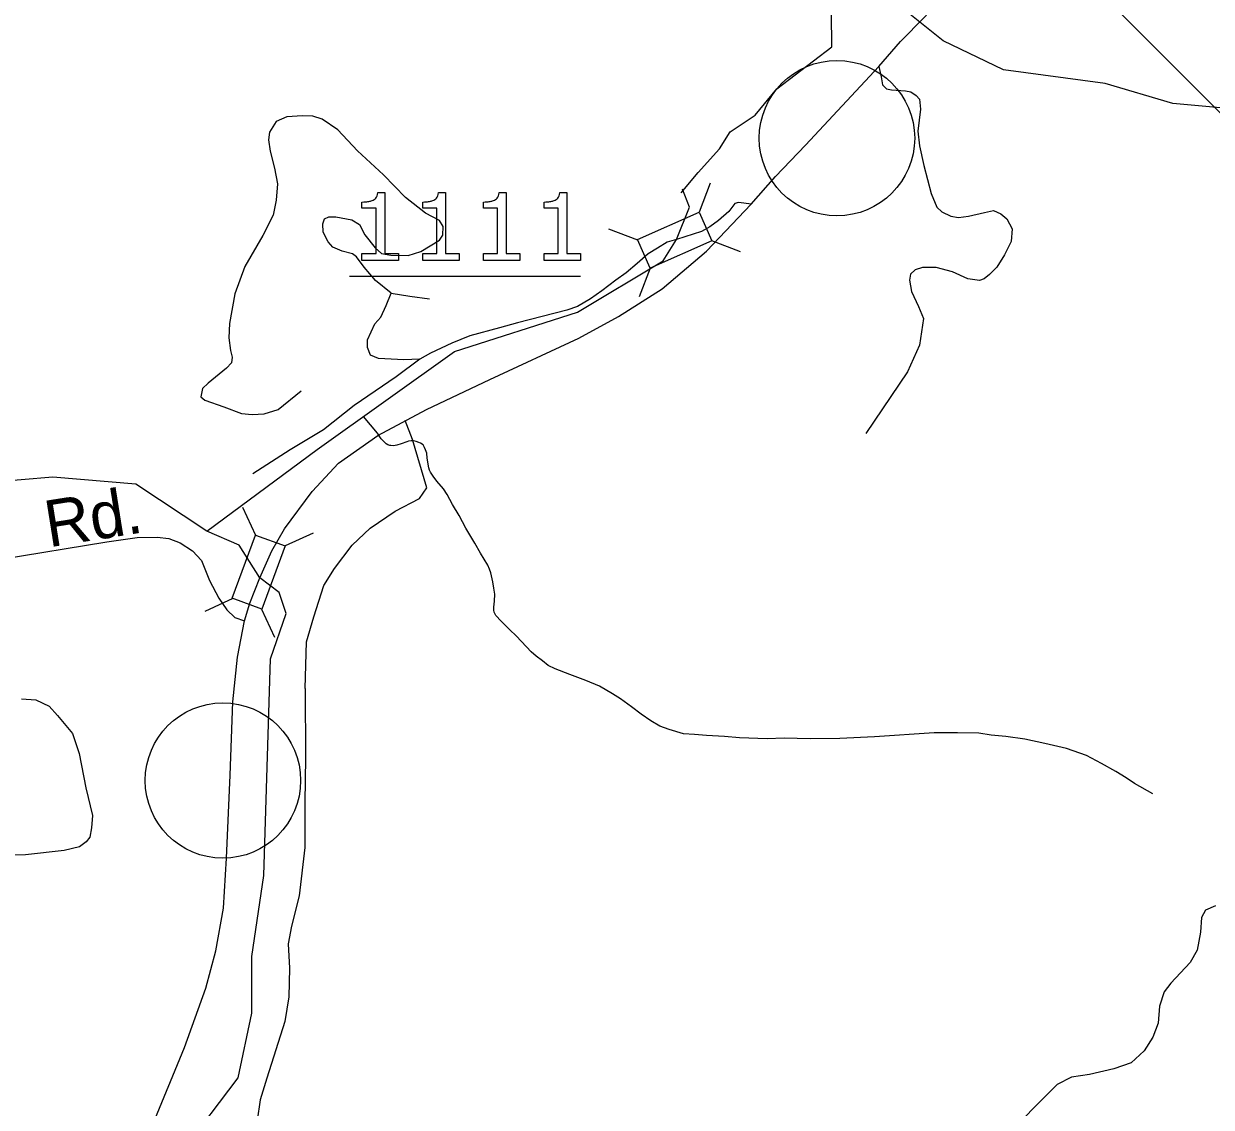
# Model space of a CAD drawing. Extents: x 1190067 to 1192950, y 891516 to 893460.
# Drawn here: x 1190882.9 to 1190959.3, y 893231.2 to 893300.9 of the extents above; entities that cross this region are included whole.
import ezdxf

# ---------------------------------------------------------------- set-up
doc = ezdxf.new("R2010")
doc.units = 0
doc.layers.add('Default', color=7, linetype='Continuous')
doc.layers.add('Prop DSN Text', color=7, linetype='Continuous')

msp = doc.modelspace()

# ---------------------------------------------------------------- linework, layer by layer
at = {"layer": 'Default'}
for p, q in [((1190960.312, 893294.828), (1190948.657, 893306.483)), ((1190927.1, 893290.667), (1190926.392, 893288.817)), ((1190922.445, 893287.017), (1190920.595, 893287.725)), ((1190929.067, 893286.258), (1190927.217, 893286.967)), ((1190923.252, 893285.208), (1190922.544, 893283.358)), ((1190903.895, 893284.692), (1190918.776, 893284.692)), ((1190897.026, 893269.823), (1190897.856, 893268.025)), ((1190901.556, 893268.154), (1190899.757, 893267.324)), ((1190896.391, 893263.941), (1190894.592, 893263.111)), ((1190898.249, 893263.257), (1190899.079, 893261.459))]:
    msp.add_line(p, q, dxfattribs=at)
for points in [[(1190929.742, 893289.335), (1190931.321, 893291.099), (1190933.231, 893293.132), (1190937.963, 893298.187), (1190939.364, 893299.797), (1190940.907, 893301.365), (1190943.539, 893304.28), (1190944.886, 893306.094), (1190945.938, 893307.784), (1190946.673, 893309.328), (1190947.395, 893311.141), (1190947.934, 893312.978), (1190948.717, 893316.163), (1190949.501, 893318.834), (1190950.113, 893320.28), (1190950.799, 893321.411)], [(1190925.252, 893290.053), (1190926.327, 893291.359), (1190927.709, 893292.896), (1190928.4, 893293.972), (1190930.013, 893295.048), (1190931.395, 893296.739), (1190934.934, 893299.456), (1190934.899, 893303.824)], [(1190980.698, 893248.449), (1190979.491, 893247.036), (1190979.736, 893245.425), (1190981.503, 893246.077), (1190983.883, 893247.925), (1190988.976, 893247.078), (1190989.711, 893247.637), (1190989.396, 893251.894), (1190988.398, 893253.063), (1190988.573, 893253.634), (1190985.196, 893258.527), (1190981.713, 893269.914), (1190981.344, 893272.506), (1190978.598, 893279.282), (1190976.358, 893282.428), (1190970.811, 893287.999), (1190966.348, 893289.983), (1190961.814, 893295.359), (1190956.881, 893295.802), (1190952.522, 893297.095), (1190945.977, 893297.974), (1190942.094, 893299.83), (1190938.664, 893302.599), (1190934.899, 893303.824)], [(1190980.698, 893248.449), (1190979.491, 893247.036), (1190979.736, 893245.425), (1190981.503, 893246.077), (1190983.883, 893247.925), (1190988.976, 893247.078), (1190989.711, 893247.637), (1190989.396, 893251.894), (1190988.398, 893253.063), (1190988.573, 893253.634), (1190985.196, 893258.527), (1190981.713, 893269.914), (1190981.344, 893272.506), (1190978.598, 893279.282), (1190976.358, 893282.428), (1190970.811, 893287.999), (1190966.348, 893289.983), (1190961.814, 893295.359), (1190956.881, 893295.802), (1190952.522, 893297.095), (1190945.977, 893297.974), (1190942.094, 893299.83), (1190938.664, 893302.599), (1190934.899, 893303.824)], [(1190937.963, 893298.187), (1190938.113, 893297.525), (1190938.204, 893297.013), (1190938.444, 893296.742), (1190938.775, 893296.682), (1190939.677, 893296.622), (1190940.008, 893296.562), (1190940.369, 893296.321), (1190940.58, 893296.08), (1190940.64, 893295.448), (1190940.459, 893294.034), (1190940.58, 893293.071), (1190940.85, 893291.807), (1190941.331, 893290.001), (1190941.692, 893289.128), (1190942.023, 893288.827), (1190942.595, 893288.556), (1190943.076, 893288.466), (1190943.737, 893288.556), (1190944.76, 893288.797), (1190945.331, 893288.917), (1190945.813, 893288.707), (1190946.204, 893288.376), (1190946.534, 893287.744), (1190946.474, 893286.931), (1190946.038, 893286.058), (1190945.557, 893285.276), (1190945.076, 893284.794), (1190944.745, 893284.523), (1190944.444, 893284.403), (1190943.692, 893284.523), (1190942.7, 893284.975), (1190941.647, 893285.246), (1190940.775, 893285.246), (1190940.294, 893285.095), (1190939.993, 893284.824), (1190939.933, 893284.433), (1190940.053, 893283.711), (1190940.504, 893282.748), (1190940.835, 893281.965), (1190940.58, 893280.25), (1190939.798, 893278.534), (1190937.121, 893274.561)], [(1190906.586, 893283.602), (1190905.583, 893284.41), (1190904.848, 893285.268), (1190904.358, 893285.929), (1190904.089, 893286.125), (1190903.428, 893286.297), (1190902.84, 893286.566), (1190902.522, 893286.909), (1190902.216, 893287.522), (1190902.191, 893288.061), (1190902.289, 893288.379), (1190902.583, 893288.502), (1190903.024, 893288.502), (1190904.052, 893288.306), (1190904.542, 893288.012), (1190904.885, 893287.35), (1190905.546, 893286.517), (1190905.962, 893286.15), (1190906.574, 893286.052), (1190907.676, 893286.027), (1190908.484, 893286.272), (1190909.684, 893287.007), (1190909.904, 893287.326), (1190909.928, 893287.889), (1190909.684, 893288.281), (1190908.802, 893288.747), (1190907.505, 893289.751), (1190906.084, 893291.221), (1190904.42, 893292.765), (1190903.146, 893294.113), (1190902.155, 893294.799), (1190901.543, 893294.995), (1190900.882, 893295.019), (1190899.878, 893294.946), (1190899.192, 893294.652), (1190898.751, 893293.966), (1190898.703, 893293.475), (1190898.8, 893292.74), (1190899.07, 893291.638), (1190899.266, 893290.633), (1190899.192, 893289.58), (1190898.996, 893288.624), (1190898.335, 893287.301), (1190897.172, 893285.317), (1190896.536, 893283.553), (1190896.193, 893281.641), (1190896.132, 893280.71), (1190896.254, 893279.902), (1190896.352, 893279.485), (1190896.303, 893279.118), (1190895.985, 893278.775), (1190894.81, 893277.795), (1190894.442, 893277.452), (1190894.344, 893276.913), (1190894.589, 893276.717), (1190895.813, 893276.276), (1190896.964, 893275.859), (1190897.65, 893275.786), (1190898.409, 893275.835), (1190899.315, 893276.104), (1190900.784, 893277.305)], [(1190905.721, 893290.072), (1190906.174, 893290.072), (1190906.174, 893286.151), (1190907.062, 893286.151), (1190907.062, 893285.707)], [(1190909.626, 893290.072), (1190910.079, 893290.072), (1190910.079, 893286.151), (1190910.967, 893286.151), (1190910.967, 893285.707)], [(1190913.531, 893290.072), (1190913.984, 893290.072), (1190913.984, 893286.151), (1190914.871, 893286.151), (1190914.871, 893285.707)], [(1190917.435, 893290.072), (1190917.888, 893290.072), (1190917.888, 893286.151), (1190918.776, 893286.151), (1190918.776, 893285.707)], [(1190924.937, 893287.044), (1190925.782, 893289.139), (1190925.328, 893290.283)], [(1190898.144, 893265.261), (1190898.915, 893267.019), (1190899.722, 893268.432), (1190901.493, 893270.825), (1190903.2, 893272.656), (1190905.72, 893274.425), (1190908.854, 893276.115), (1190912.924, 893278.032), (1190918.65, 893280.699), (1190921.214, 893282.083), (1190924.03, 893283.885), (1190926.868, 893286.307), (1190929.742, 893289.335)], [(1190907.062, 893285.707), (1190904.708, 893285.707), (1190904.708, 893286.151), (1190905.613, 893286.151), (1190905.613, 893289.067), (1190904.708, 893289.067), (1190904.708, 893289.464)], [(1190910.967, 893285.707), (1190908.612, 893285.707), (1190908.612, 893286.151), (1190909.518, 893286.151), (1190909.518, 893289.067), (1190908.612, 893289.067), (1190908.612, 893289.464)], [(1190914.871, 893285.707), (1190912.517, 893285.707), (1190912.517, 893286.151), (1190913.423, 893286.151), (1190913.423, 893289.067), (1190912.517, 893289.067), (1190912.517, 893289.464)], [(1190918.776, 893285.707), (1190916.422, 893285.707), (1190916.422, 893286.151), (1190917.327, 893286.151), (1190917.327, 893289.067), (1190916.422, 893289.067), (1190916.422, 893289.464)], [(1190929.742, 893289.335), (1190929.265, 893289.384), (1190928.922, 893289.433), (1190928.702, 893289.359), (1190928.31, 893288.845), (1190927.649, 893288.281), (1190927.086, 893287.865), (1190926.547, 893287.571), (1190924.937, 893287.044)], [(1190894.728, 893268.273), (1190901.828, 893273.53), (1190910.66, 893279.839), (1190918.574, 893282.376), (1190924.092, 893285.684), (1190924.937, 893287.044)], [(1190924.937, 893287.044), (1190924.35, 893286.885), (1190923.713, 893286.493), (1190923.125, 893286.125), (1190922.415, 893285.513), (1190921.705, 893284.9), (1190921.044, 893284.435), (1190920.138, 893283.749), (1190919.404, 893283.234), (1190918.571, 893282.744), (1190917.886, 893282.499), (1190914.703, 893281.69), (1190913.55, 893281.354)], [(1190908.423, 893279.338), (1190907.394, 893279.314), (1190905.778, 893279.387), (1190905.264, 893279.608), (1190905.068, 893280.098), (1190905.068, 893280.588), (1190905.534, 893281.617), (1190905.925, 893282.058), (1190906.268, 893282.793), (1190906.586, 893283.602)], [(1190906.586, 893283.602), (1190907.786, 893283.406), (1190909.059, 893283.234)], [(1190913.55, 893281.354), (1190911.655, 893280.857), (1190910.479, 893280.367), (1190909.108, 893279.73), (1190908.423, 893279.338), (1190906.905, 893278.211), (1190904.211, 893276.374), (1190902.228, 893274.806), (1190900.086, 893273.507), (1190897.686, 893271.963)], [(1190955.591, 893251.372), (1190954.418, 893252.032), (1190953.867, 893252.398), (1190953.214, 893252.8), (1190952.281, 893253.317), (1190951.314, 893253.834), (1190950.033, 893254.288), (1190948.639, 893254.605), (1190947.351, 893254.885), (1190946.131, 893255.059), (1190945.187, 893255.154), (1190944.385, 893255.282), (1190943.019, 893255.284), (1190941.512, 893255.289), (1190937.689, 893255.041), (1190935.444, 893254.928), (1190933.551, 893254.909), (1190931.872, 893254.957), (1190930.785, 893254.916), (1190929, 893254.964), (1190928.022, 893255.061), (1190926.868, 893255.127), (1190926.1, 893255.183), (1190925.4, 893255.237), (1190924.462, 893255.508), (1190923.874, 893255.732), (1190923.289, 893256.064), (1190922.67, 893256.5), (1190922.052, 893256.972), (1190921.329, 893257.481), (1190920.814, 893257.81), (1190919.985, 893258.289), (1190919.119, 893258.662), (1190918.08, 893259.041), (1190917.143, 893259.416), (1190916.695, 893259.638), (1190916.316, 893259.929), (1190915.905, 893260.219), (1190915.597, 893260.508), (1190914.642, 893261.515), (1190914.199, 893261.947), (1190913.928, 893262.234), (1190913.654, 893262.487), (1190913.313, 893262.848), (1190913.214, 893263.06), (1190913.184, 893263.2), (1190913.189, 893263.375), (1190913.234, 893263.761), (1190913.245, 893264.215), (1190913.185, 893264.601), (1190913.126, 893265.024), (1190913.002, 893265.588), (1190912.904, 893265.835), (1190912.805, 893266.083), (1190912.337, 893266.867), (1190911.967, 893267.507), (1190911.398, 893268.467), (1190910.966, 893269.286), (1190910.53, 893269.998), (1190910.198, 893270.637), (1190909.961, 893270.994), (1190909.52, 893271.496), (1190909.283, 893271.817), (1190909.114, 893272.068), (1190909.05, 893272.21), (1190909.016, 893272.35), (1190908.894, 893272.983), (1190908.869, 893273.301), (1190908.804, 893273.511), (1190908.736, 893273.654), (1190908.639, 893273.832), (1190908.465, 893273.941), (1190908.361, 893273.979), (1190908.187, 893274.055), (1190908.015, 893274.094), (1190907.875, 893274.098), (1190907.697, 893274.067), (1190907.593, 893274.035), (1190907.238, 893273.904), (1190906.956, 893273.807), (1190906.744, 893273.776), (1190906.568, 893273.782), (1190906.498, 893273.785), (1190906.36, 893273.823), (1190906.258, 893273.897), (1190906.12, 893274.04), (1190905.949, 893274.22), (1190905.716, 893274.575), (1190904.805, 893275.657)], [(1190901.047, 893258.154), (1190901.148, 893261.153), (1190901.609, 893262.767), (1190902.243, 893264.785), (1190902.934, 893265.881), (1190904.086, 893267.38), (1190905.239, 893268.475), (1190906.852, 893269.571), (1190908.408, 893270.378), (1190908.869, 893271.07), (1190907.947, 893274.184), (1190907.486, 893275.395)], [(1190894.728, 893268.273), (1190890.155, 893271.301), (1190884.816, 893271.751), (1190874.612, 893270.903)], [(1190898.144, 893265.261), (1190896.797, 893267.365), (1190894.728, 893268.273)], [(1190881.486, 893266.482), (1190888.282, 893267.587), (1190890.248, 893267.863), (1190891.524, 893267.897), (1190892.283, 893267.794), (1190893.007, 893267.518), (1190893.8, 893267), (1190894.387, 893266.379), (1190894.904, 893265.101), (1190895.491, 893263.962), (1190896.008, 893263.203), (1190896.525, 893262.72), (1190897.158, 893262.508)], [(1190888.631, 893168.483), (1190885.92, 893174.798), (1190884.708, 893176.878), (1190885.66, 893181.124), (1190888.518, 893185.457), (1190889.731, 893188.057), (1190889.471, 893191.35), (1190887.392, 893195.337), (1190889.471, 893200.103), (1190890.077, 893205.563), (1190889.99, 893208.249), (1190891.896, 893213.535), (1190892.588, 893220.079), (1190892.329, 893223.285), (1190893.195, 893228.398), (1190896.745, 893233.078), (1190897.611, 893237.238), (1190897.611, 893240.903), (1190898.391, 893246.103), (1190898.824, 893260.056), (1190899.837, 893262.969), (1190899.376, 893264.324), (1190898.144, 893265.261)], [(1190897.158, 893262.508), (1190897.489, 893263.632), (1190898.144, 893265.261)], [(1190884.683, 893196.746), (1190885.345, 893200.465), (1190885.907, 893204.127), (1190887.463, 893212.343), (1190888.183, 893216.235), (1190889.062, 893220.762), (1190889.811, 893225.115), (1190890.33, 893227.306), (1190891.237, 893230.045), (1190893.283, 893235.033), (1190894.666, 893238.867), (1190895.299, 893241.26), (1190895.789, 893243.999), (1190895.991, 893247.228), (1190896.236, 893252.561), (1190896.408, 893257.289), (1190896.697, 893260.172), (1190897.158, 893262.508)], [(1190901.047, 893258.154), (1190901.076, 893253.686), (1190901.032, 893250.803), (1190901.032, 893247.92), (1190900.658, 893244.806), (1190900.183, 893242.845), (1190899.952, 893241.721), (1190900.039, 893240.135), (1190899.995, 893238.29), (1190899.736, 893236.705), (1190898.584, 893233.072), (1190898.166, 893231.659), (1190897.964, 893230.333), (1190897.935, 893228.286), (1190897.244, 893224.913), (1190896.308, 893222.664), (1190896.106, 893221.828), (1190896.106, 893220.272), (1190895.876, 893217.85), (1190895.559, 893216.293), (1190894.421, 893212.43)], [(1190882.797, 893257.49), (1190883.728, 893257.421), (1190884.591, 893257.007), (1190885.108, 893256.42), (1190886.074, 893255.247), (1190886.522, 893253.97), (1190886.936, 893251.761), (1190887.367, 893249.966), (1190887.298, 893249.172), (1190887.195, 893248.585), (1190886.954, 893248.274), (1190886.54, 893247.964), (1190885.539, 893247.722), (1190883.056, 893247.446), (1190879.331, 893247.342)], [(1190959.618, 893244.166), (1190958.98, 893243.877), (1190958.719, 893243.413), (1190958.661, 893242.456), (1190958.43, 893241.296), (1190957.995, 893240.514), (1190956.749, 893239.18), (1190956.315, 893238.629), (1190956.025, 893237.701), (1190955.938, 893236.6), (1190955.59, 893235.701), (1190955.04, 893234.831), (1190954.2, 893234.048), (1190953.07, 893233.671), (1190951.505, 893233.295), (1190950.361, 893233.121), (1190949.434, 893232.657), (1190947.927, 893231.149), (1190946.218, 893229.381), (1190944.943, 893227.931), (1190943.596, 893226.424), (1190943.191, 893225.902), (1190942.93, 893225.148)]]:
    msp.add_lwpolyline(points, dxfattribs=at)
for points in [[(1190927.217, 893286.967), (1190923.256, 893285.199), (1190922.43, 893287.05), (1190926.392, 893288.817)], [(1190899.757, 893267.324), (1190898.258, 893263.254), (1190896.356, 893263.954), (1190897.856, 893268.025)]]:
    msp.add_lwpolyline(points, close=True, dxfattribs=at)
for points in [[(1190904.708, 893289.464), (1190904.892, 893289.464), (1190905.102, 893289.495), (1190905.312, 893289.526), (1190905.42, 893289.584), (1190905.555, 893289.657), (1190905.632, 893289.769), (1190905.71, 893289.882), (1190905.721, 893290.072)], [(1190908.612, 893289.464), (1190908.796, 893289.464), (1190909.007, 893289.495), (1190909.217, 893289.526), (1190909.325, 893289.584), (1190909.46, 893289.657), (1190909.537, 893289.769), (1190909.614, 893289.882), (1190909.626, 893290.072)], [(1190912.517, 893289.464), (1190912.701, 893289.464), (1190912.911, 893289.495), (1190913.122, 893289.526), (1190913.23, 893289.584), (1190913.364, 893289.657), (1190913.442, 893289.769), (1190913.519, 893289.882), (1190913.531, 893290.072)], [(1190916.422, 893289.464), (1190916.606, 893289.464), (1190916.816, 893289.495), (1190917.026, 893289.526), (1190917.134, 893289.584), (1190917.269, 893289.657), (1190917.346, 893289.769), (1190917.424, 893289.882), (1190917.435, 893290.072)]]:
    msp.add_open_spline(points, degree=3, dxfattribs=at)
at = {"layer": 'Prop DSN Text'}
for centre in [(1190935.265, 893293.573), (1190935.265, 893293.573), (1190895.762, 893252.222), (1190895.762, 893252.222)]:
    msp.add_circle(centre, 5, dxfattribs=at)

# ---------------------------------------------------------------- texts
at = {"layer": 'Default'}
msp.add_text('Rd.', height=3, rotation=9.05705, dxfattribs=at).set_placement((1190884.554, 893267.227))

doc.saveas('drawing.dxf')
